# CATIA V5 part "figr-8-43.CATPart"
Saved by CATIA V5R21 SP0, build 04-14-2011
Part number: Part1
Bounding box of the stored display mesh (mm): x -50 to 50, y -50 to 50, z 0 to 25
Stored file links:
  D:\CATIA V5R21 E-RESOURCES\CATIA-V5R21\catia-v5r21-prt\c08-catia-v5r20-prt\c08-catia-v5r21-figr-8-43.CATPart
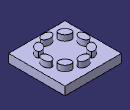
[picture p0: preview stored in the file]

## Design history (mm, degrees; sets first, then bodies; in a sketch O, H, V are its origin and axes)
Body1 (main body)
  Sketch1 on xy-plane, origin (0, 0, 0), H (1, 0, 0), V (0, 1, 0)
    line L1 (-50, 50) -> (50, 50)
    line L2 (50, 50) -> (50, -50)
    line L3 (50, -50) -> (-50, -50)
    line L4 (-50, -50) -> (-50, 50)
    axis line L5 (50, -50) -> (-50, 50)
    length L2 = 100
    length L3 = 100
    horizontal: L1 H, L3 H
    vertical: L2 V, L4 V
    midpoint: L5 O
  Pad1: profile Sketch1, direction (0, 0, 1), length 15
  Sketch2 on face of Pad1, origin (0, 0, 15), H (1, 0, 0), V (0, 1, 0)
    point P1 (0, -32.9864)
    ellipse A1 centre (0, -32.9864) semi-axes 9.9006, 6.5465 rotation 0
    point P2 (0, -26.4399)
    coincidence: P1 V, P2 V, A1 P2
  Pad2: profile Sketch2, direction (0, 0, 1), length 10
  CircPattern1: of Pad2, instances 8, angular step 45 {= 360.0*1 deg/CircPattern1.AngularNumber}, axis from edge of Sketch3
  Sketch3 on yz-plane, origin (0, 0, 0), H (0, 1, 0), V (0, 0, 1)
    line L1 (0, 0) -> (0, 18.4864)
    vertical: L1 V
